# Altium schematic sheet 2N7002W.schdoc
size 127 x 101 mm
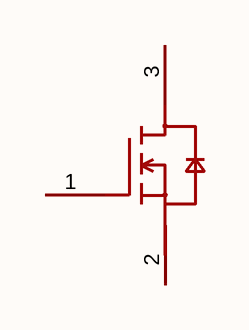
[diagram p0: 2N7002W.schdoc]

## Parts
Q?  2n7002w_c190607  [SOT-323-3_L2.2-W1.3-P1.30-LS2.1-BL]  (value not drawn)

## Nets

Not connected (* = marked no-connect by the designer): Q? 1(G) 2(S) 3(D)

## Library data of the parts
Q? = 2n7002w_c190607: 数量:1个N沟道;漏源电压(Vdss):60V;连续漏极电流(Id):115mA;导通电阻(RDS(on)):5Ω@10V;耗散功率(Pd):200mW;阈值电压(Vgs(th)):2.5V;; Manufacturer: CJ(江苏长电/长晶); AddInBom: yes; ModelId: 59529c0d6fc749f28f2d0659e12986b4; ModelName: SOT-323-3_L2.0-W1.3-H1.0-LS2.1-P1.30; ModelTransform: 78.74,82.677,0,0,0,0,0.004,0.004,0; Number: 1个N沟道; Drain to Source Voltage: 60V; Current - Continuous Drain(Id): 115mA; RDS(on): 5Ω@10V; Pd - Power Dissipation: 200mW; Gate Threshold Voltage (Vgs(th)): 2.5V; Input Capacitance(Ciss): 50pF; Reverse Transfer Capacitance (Crss@Vds): 5pF; Type: N沟道; Output Capacitance(Coss): 25pF; Vgs: ±20V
